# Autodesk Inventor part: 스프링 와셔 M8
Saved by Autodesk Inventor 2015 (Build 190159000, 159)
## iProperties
Created: 2024-12
Part Number: 스프링 와셔 M8
Material: 일반
Document SubType Name: Modeling
Designer: 102-5
Density: 1 g/cm^3
Appearance: 기본값
Author: 102-5
Author: jhkim
Description: 스프링 잠금 와셔
Creation Date: 2024-11-28
Sending System: Autodesk Inventor 2025
Preprocessor: ST-DEVELOPER v20
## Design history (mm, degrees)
node "스프링 와셔 M81"
body "Solid1"
node "기준1"
